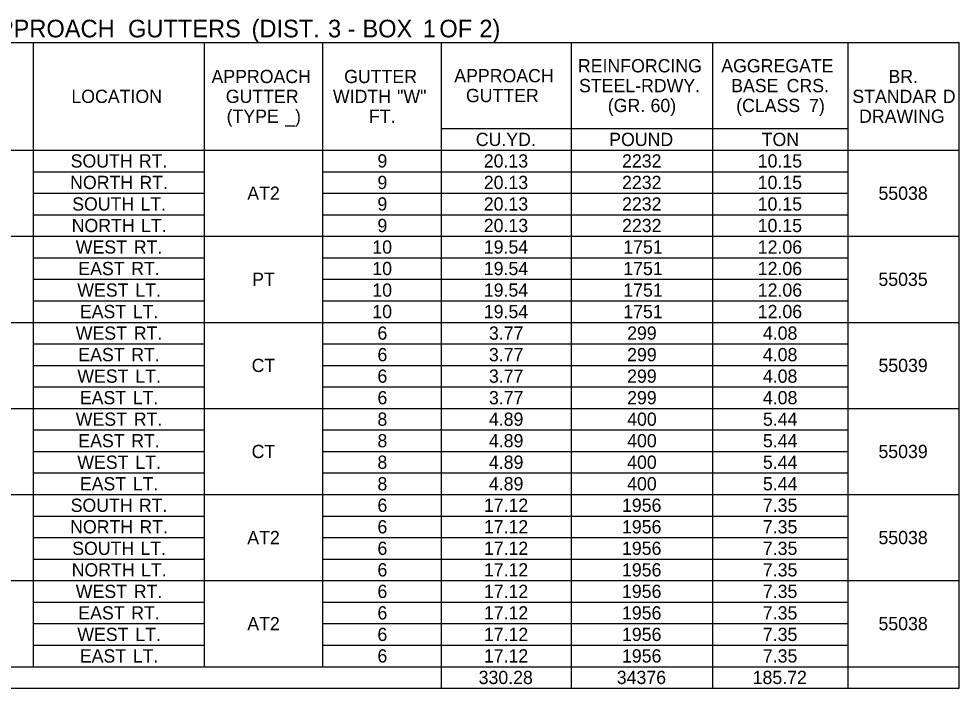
# Model space of a CAD drawing. Extents: x 544478 to 1930787, y -1948294 to 596640.
# Drawn here: x 559788.1 to 560214, y -1946463.7 to -1946160.4 of the extents above; entities that cross this region are included whole.
import ezdxf

# ---------------------------------------------------------------- set-up
doc = ezdxf.new("R2010")
doc.units = 0
doc.layers.add('Default', color=7, linetype='Continuous')

msp = doc.modelspace()

# ---------------------------------------------------------------- linework, layer by layer
at = {"layer": 'Default'}
for p, q in [((559563.64, -1946171.21), (560213.97, -1946171.21)), ((559794.72, -1946453.96), (559794.72, -1946171.21)), ((559872.23, -1946453.96), (559872.23, -1946171.21)), ((559925.85, -1946453.96), (559925.85, -1946171.21)), ((559979.48, -1946463.71), (559979.48, -1946171.21)), ((560038.47, -1946453.96), (560038.47, -1946171.21)), ((560102.33, -1946453.96), (560102.33, -1946171.21)), ((560163.75, -1946463.71), (560163.75, -1946171.21)), ((560213.97, -1946463.71), (560213.97, -1946171.21)), ((559979.48, -1946210.21), (560163.75, -1946210.21)), ((560038.47, -1946219.96), (560038.47, -1946210.21)), ((560102.33, -1946219.96), (560102.33, -1946210.21)), ((560163.75, -1946219.96), (560163.75, -1946210.21)), ((559563.64, -1946219.96), (560213.97, -1946219.96)), ((560163.75, -1946219.96), (560213.97, -1946219.96)), ((559794.72, -1946229.71), (559872.23, -1946229.71)), ((559925.85, -1946229.71), (560163.75, -1946229.71)), ((559979.48, -1946229.71), (560102.33, -1946229.71)), ((560102.33, -1946229.71), (560163.75, -1946229.71)), ((559794.72, -1946239.46), (559872.23, -1946239.46)), ((559925.85, -1946239.46), (560163.75, -1946239.46)), ((559979.48, -1946239.46), (560102.33, -1946239.46)), ((560102.33, -1946239.46), (560163.75, -1946239.46)), ((559794.72, -1946249.21), (559872.23, -1946249.21)), ((559925.85, -1946249.21), (560163.75, -1946249.21)), ((559979.48, -1946249.21), (560102.33, -1946249.21)), ((560102.33, -1946249.21), (560163.75, -1946249.21)), ((559563.64, -1946258.96), (560213.97, -1946258.96)), ((559872.23, -1946258.96), (559979.48, -1946258.96)), ((559979.48, -1946258.96), (560102.33, -1946258.96)), ((560038.47, -1946336.96), (560038.47, -1946258.96)), ((560102.33, -1946258.96), (560213.97, -1946258.96)), ((559794.72, -1946268.71), (559872.23, -1946268.71)), ((559925.85, -1946268.71), (560163.75, -1946268.71)), ((559794.72, -1946278.46), (559872.23, -1946278.46)), ((559925.85, -1946278.46), (560163.75, -1946278.46)), ((559794.72, -1946288.21), (559872.23, -1946288.21)), ((559925.85, -1946288.21), (560163.75, -1946288.21)), ((559563.64, -1946297.96), (560213.97, -1946297.96)), ((559872.23, -1946297.96), (560163.75, -1946297.96)), ((560163.75, -1946297.96), (560213.97, -1946297.96)), ((559794.72, -1946307.71), (559872.23, -1946307.71)), ((559925.85, -1946307.71), (560163.75, -1946307.71)), ((559794.72, -1946317.46), (559872.23, -1946317.46)), ((559925.85, -1946317.46), (560163.75, -1946317.46)), ((559794.72, -1946327.21), (559872.23, -1946327.21)), ((559925.85, -1946327.21), (560163.75, -1946327.21)), ((559563.64, -1946336.96), (560213.97, -1946336.96)), ((559872.23, -1946336.96), (560163.75, -1946336.96)), ((560163.75, -1946336.96), (560213.97, -1946336.96)), ((559794.72, -1946346.71), (559872.23, -1946346.71)), ((559925.85, -1946346.71), (560163.75, -1946346.71)), ((559979.48, -1946346.71), (560102.33, -1946346.71)), ((560102.33, -1946346.71), (560163.75, -1946346.71)), ((559794.72, -1946356.46), (559872.23, -1946356.46)), ((559925.85, -1946356.46), (560163.75, -1946356.46)), ((559979.48, -1946356.46), (560102.33, -1946356.46)), ((560102.33, -1946356.46), (560163.75, -1946356.46)), ((559794.72, -1946366.21), (559872.23, -1946366.21)), ((559925.85, -1946366.21), (560163.75, -1946366.21)), ((559979.48, -1946366.21), (560102.33, -1946366.21)), ((560102.33, -1946366.21), (560163.75, -1946366.21)), ((559563.64, -1946375.96), (560213.97, -1946375.96)), ((559872.23, -1946375.96), (559979.48, -1946375.96)), ((559979.48, -1946375.96), (560102.33, -1946375.96)), ((560038.47, -1946414.96), (560038.47, -1946375.96)), ((560102.33, -1946375.96), (560213.97, -1946375.96)), ((559794.72, -1946385.71), (559872.23, -1946385.71)), ((559925.85, -1946385.71), (560163.75, -1946385.71)), ((559794.72, -1946395.46), (559872.23, -1946395.46)), ((559925.85, -1946395.46), (560163.75, -1946395.46)), ((559794.72, -1946405.21), (559872.23, -1946405.21)), ((559925.85, -1946405.21), (560163.75, -1946405.21)), ((559563.64, -1946414.96), (560213.97, -1946414.96)), ((559872.23, -1946414.96), (560163.75, -1946414.96)), ((560163.75, -1946414.96), (560213.97, -1946414.96)), ((559794.72, -1946424.71), (559872.23, -1946424.71)), ((559925.85, -1946424.71), (560163.75, -1946424.71)), ((559979.48, -1946424.71), (560102.33, -1946424.71)), ((560102.33, -1946424.71), (560163.75, -1946424.71)), ((559794.72, -1946434.46), (559872.23, -1946434.46)), ((559925.85, -1946434.46), (560163.75, -1946434.46)), ((559979.48, -1946434.46), (560102.33, -1946434.46)), ((560102.33, -1946434.46), (560163.75, -1946434.46)), ((559794.72, -1946444.21), (559872.23, -1946444.21)), ((559925.85, -1946444.21), (560163.75, -1946444.21)), ((559979.48, -1946444.21), (560102.33, -1946444.21)), ((560102.33, -1946444.21), (560163.75, -1946444.21)), ((559563.64, -1946453.96), (560213.97, -1946453.96)), ((559872.23, -1946453.96), (559979.48, -1946453.96)), ((559979.48, -1946453.96), (560102.33, -1946453.96)), ((559979.48, -1946463.71), (559979.48, -1946453.96)), ((560038.47, -1946463.71), (560038.47, -1946453.96)), ((560038.47, -1946463.71), (560038.47, -1946453.96)), ((560102.33, -1946453.96), (560213.97, -1946453.96)), ((560102.33, -1946463.71), (560102.33, -1946453.96)), ((560102.33, -1946463.71), (560102.33, -1946453.96)), ((560163.75, -1946463.71), (560163.75, -1946453.96)), ((559563.64, -1946463.71), (560213.97, -1946463.71))]:
    msp.add_line(p, q, dxfattribs=at)

# ---------------------------------------------------------------- texts
for s, height, p in [('APPROACH', 8, (559771.47, -1946168.87)), (' GUTTERS', 8, (559834.58, -1946168.87)), (' (DIST.', 8, (559890.55, -1946168.87)), (' 3', 8, (559925.17, -1946168.87)), (' BOX', 8, (559940.75, -1946168.87)), (' 1', 8, (559968.07, -1946168.87)), (' OF', 8, (559975.58, -1946168.87)), (' 2)', 8, (559993.69, -1946168.87)), (' -', 8, (559934.01, -1946168.87)), ('REINFORCING', 6, (560041.31, -1946184.71)), ('AGGREGATE', 6, (560106.23, -1946184.71)), ('APPROACH', 6, (559875.37, -1946189.58)), ('GUTTER', 6, (559935.45, -1946189.58)), ('APPROACH', 6, (559985.31, -1946189.21)), ('BR.', 6, (560181.93, -1946189.58)), ('STEEL-RDWY.', 6, (560041.81, -1946193.71)), ('BASE', 6, (560110.71, -1946193.71)), (' CRS.', 6, (560133.59, -1946193.71)), ('LOCATION', 6, (559811.92, -1946198.58)), ('GUTTER', 6, (559881.83, -1946198.58)), ('WIDTH', 6, (559930.37, -1946198.58)), (' "W"', 6, (559957.19, -1946198.58)), ('GUTTER', 6, (559990.6, -1946198.21)), ('STANDAR', 6, (560165.57, -1946198.58)), ('D', 6, (560206.52, -1946198.58)), ('(GR.', 6, (560054.84, -1946202.71)), (' 60)', 6, (560071.96, -1946202.71)), ('(CLASS', 6, (560112.97, -1946202.71)), (' 7)', 6, (560143.77, -1946202.71)), ('(TYPE', 6, (559882.23, -1946207.58)), (' _)', 6, (559906.51, -1946207.58)), ('FT.', 6, (559946.67, -1946207.58)), ('DRAWING', 6, (560168.62, -1946207.58)), ('CU.YD.', 6, (559995.06, -1946218.08)), ('POUND', 6, (560055.47, -1946218.08)), ('TON', 6, (560124.53, -1946218.08)), ('SOUTH', 6, (559811.59, -1946227.83)), (' RT.', 6, (559840.26, -1946227.83)), ('9', 6, (559950.52, -1946227.83)), ('20.13', 6, (559998.68, -1946227.83)), ('2232', 6, (560061.3, -1946227.83)), ('10.15', 6, (560122.73, -1946227.83)), ('NORTH', 6, (559811.36, -1946237.58)), (' RT.', 6, (559840.49, -1946237.58)), ('9', 6, (559950.52, -1946237.58)), ('20.13', 6, (559998.68, -1946237.58)), ('2232', 6, (560061.3, -1946237.58)), ('10.15', 6, (560122.73, -1946237.58)), ('AT2', 6, (559891.58, -1946242.46)), ('55038', 6, (560177.4, -1946242.46)), ('SOUTH', 6, (559812.29, -1946247.33)), (' LT.', 6, (559840.96, -1946247.33)), ('9', 6, (559950.52, -1946247.33)), ('20.13', 6, (559998.68, -1946247.33)), ('2232', 6, (560061.3, -1946247.33)), ('10.15', 6, (560122.73, -1946247.33)), ('NORTH', 6, (559812.06, -1946257.08)), (' LT.', 6, (559841.19, -1946257.08)), ('9', 6, (559950.52, -1946257.08)), ('20.13', 6, (559998.68, -1946257.08)), ('2232', 6, (560061.3, -1946257.08)), ('10.15', 6, (560122.73, -1946257.08)), ('WEST', 6, (559813.9, -1946266.83)), (' RT.', 6, (559837.95, -1946266.83)), ('10', 6, (559948.21, -1946266.83)), ('19.54', 6, (559998.69, -1946266.83)), ('1751', 6, (560061.85, -1946266.83)), ('12.06', 6, (560122.75, -1946266.83)), ('EAST', 6, (559815.06, -1946276.58)), (' RT.', 6, (559836.79, -1946276.58)), ('10', 6, (559948.21, -1946276.58)), ('19.54', 6, (559998.69, -1946276.58)), ('1751', 6, (560061.85, -1946276.58)), ('12.06', 6, (560122.75, -1946276.58)), ('PT', 6, (559893.77, -1946281.46)), ('55035', 6, (560177.38, -1946281.46)), ('WEST', 6, (559814.6, -1946286.33)), (' LT.', 6, (559838.65, -1946286.33)), ('10', 6, (559948.21, -1946286.33)), ('19.54', 6, (559998.69, -1946286.33)), ('1751', 6, (560061.85, -1946286.33)), ('12.06', 6, (560122.75, -1946286.33)), ('EAST', 6, (559815.75, -1946296.08)), (' LT.', 6, (559837.49, -1946296.08)), ('10', 6, (559948.21, -1946296.08)), ('19.54', 6, (559998.69, -1946296.08)), ('1751', 6, (560061.85, -1946296.08)), ('12.06', 6, (560122.75, -1946296.08)), ('WEST', 6, (559813.9, -1946305.83)), (' RT.', 6, (559837.95, -1946305.83)), ('6', 6, (559950.53, -1946305.83)), ('3.77', 6, (560001.01, -1946305.83)), ('299', 6, (560063.59, -1946305.83)), ('4.08', 6, (560125.07, -1946305.83)), ('EAST', 6, (559815.06, -1946315.58)), (' RT.', 6, (559836.79, -1946315.58)), ('6', 6, (559950.53, -1946315.58)), ('3.77', 6, (560001.01, -1946315.58)), ('299', 6, (560063.59, -1946315.58)), ('4.08', 6, (560125.07, -1946315.58)), ('CT', 6, (559893.54, -1946320.46)), ('55039', 6, (560177.4, -1946320.46)), ('WEST', 6, (559814.6, -1946325.33)), (' LT.', 6, (559838.65, -1946325.33)), ('6', 6, (559950.53, -1946325.33)), ('3.77', 6, (560001.01, -1946325.33)), ('299', 6, (560063.59, -1946325.33)), ('4.08', 6, (560125.07, -1946325.33)), ('EAST', 6, (559815.75, -1946335.08)), (' LT.', 6, (559837.49, -1946335.08)), ('6', 6, (559950.53, -1946335.08)), ('3.77', 6, (560001.01, -1946335.08)), ('299', 6, (560063.59, -1946335.08)), ('4.08', 6, (560125.07, -1946335.08)), ('WEST', 6, (559813.9, -1946344.83)), (' RT.', 6, (559837.95, -1946344.83)), ('8', 6, (559950.52, -1946344.83)), ('4.89', 6, (560001, -1946344.83)), ('400', 6, (560063.61, -1946344.83)), ('5.44', 6, (560125.09, -1946344.83)), ('EAST', 6, (559815.06, -1946354.58)), (' RT.', 6, (559836.79, -1946354.58)), ('8', 6, (559950.52, -1946354.58)), ('4.89', 6, (560001, -1946354.58)), ('400', 6, (560063.61, -1946354.58)), ('5.44', 6, (560125.09, -1946354.58)), ('CT', 6, (559893.54, -1946359.46)), ('55039', 6, (560177.4, -1946359.46)), ('WEST', 6, (559814.6, -1946364.33)), (' LT.', 6, (559838.65, -1946364.33)), ('8', 6, (559950.52, -1946364.33)), ('4.89', 6, (560001, -1946364.33)), ('400', 6, (560063.61, -1946364.33)), ('5.44', 6, (560125.09, -1946364.33)), ('EAST', 6, (559815.75, -1946374.08)), (' LT.', 6, (559837.49, -1946374.08)), ('8', 6, (559950.52, -1946374.08)), ('4.89', 6, (560001, -1946374.08)), ('400', 6, (560063.61, -1946374.08)), ('5.44', 6, (560125.09, -1946374.08)), ('SOUTH', 6, (559811.59, -1946383.83)), (' RT.', 6, (559840.26, -1946383.83)), ('6', 6, (559950.53, -1946383.83)), ('17.12', 6, (559998.71, -1946383.83)), ('1956', 6, (560061.27, -1946383.83)), ('7.35', 6, (560125.06, -1946383.83)), ('NORTH', 6, (559811.36, -1946393.58)), (' RT.', 6, (559840.49, -1946393.58)), ('6', 6, (559950.53, -1946393.58)), ('17.12', 6, (559998.71, -1946393.58)), ('1956', 6, (560061.27, -1946393.58)), ('7.35', 6, (560125.06, -1946393.58)), ('AT2', 6, (559891.58, -1946398.46)), ('55038', 6, (560177.4, -1946398.46)), ('SOUTH', 6, (559812.29, -1946403.33)), (' LT.', 6, (559840.96, -1946403.33)), ('6', 6, (559950.53, -1946403.33)), ('17.12', 6, (559998.71, -1946403.33)), ('1956', 6, (560061.27, -1946403.33)), ('7.35', 6, (560125.06, -1946403.33)), ('NORTH', 6, (559812.06, -1946413.08)), (' LT.', 6, (559841.19, -1946413.08)), ('6', 6, (559950.53, -1946413.08)), ('17.12', 6, (559998.71, -1946413.08)), ('1956', 6, (560061.27, -1946413.08)), ('7.35', 6, (560125.06, -1946413.08)), ('WEST', 6, (559813.9, -1946422.83)), (' RT.', 6, (559837.95, -1946422.83)), ('6', 6, (559950.53, -1946422.83)), ('17.12', 6, (559998.71, -1946422.83)), ('1956', 6, (560061.27, -1946422.83)), ('7.35', 6, (560125.06, -1946422.83)), ('EAST', 6, (559815.06, -1946432.58)), (' RT.', 6, (559836.79, -1946432.58)), ('6', 6, (559950.53, -1946432.58)), ('17.12', 6, (559998.71, -1946432.58)), ('1956', 6, (560061.27, -1946432.58)), ('7.35', 6, (560125.06, -1946432.58)), ('AT2', 6, (559891.58, -1946437.46)), ('55038', 6, (560177.4, -1946437.46)), ('WEST', 6, (559814.6, -1946442.33)), (' LT.', 6, (559838.65, -1946442.33)), ('6', 6, (559950.53, -1946442.33)), ('17.12', 6, (559998.71, -1946442.33)), ('1956', 6, (560061.27, -1946442.33)), ('7.35', 6, (560125.06, -1946442.33)), ('EAST', 6, (559815.75, -1946452.08)), (' LT.', 6, (559837.49, -1946452.08)), ('6', 6, (559950.53, -1946452.08)), ('17.12', 6, (559998.71, -1946452.08)), ('1956', 6, (560061.27, -1946452.08)), ('7.35', 6, (560125.06, -1946452.08)), ('330.28', 6, (559996.35, -1946461.83)), ('34376', 6, (560058.9, -1946461.83)), ('185.72', 6, (560120.44, -1946461.83))]:
    msp.add_text(s, height=height, dxfattribs=at).set_placement(p)

doc.saveas('drawing.dxf')
